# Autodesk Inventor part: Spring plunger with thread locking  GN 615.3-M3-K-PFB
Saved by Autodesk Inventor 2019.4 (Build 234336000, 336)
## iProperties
Created: 2021-08
Part Number: Spring plunger with thread locking  GN 615.3-M3-K-PFB
Material: Generic
Document SubType Name: Modeling
Designer: Administrator
Density: 1 g/cm^3
Appearance: Default
Title: Spring plunger with thread locking  GN 615.3-M3-K-PFB
Author: Administrator
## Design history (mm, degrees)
feature "Body1"
body "Solid1"
